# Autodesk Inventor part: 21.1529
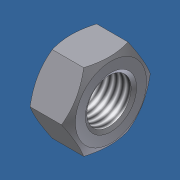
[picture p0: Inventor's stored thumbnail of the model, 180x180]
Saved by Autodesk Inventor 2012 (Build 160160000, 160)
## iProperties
Created: 2006-02
Part Number: 21.1529
Material: Steel, Mild
Description: M16 HEX NUT
Document SubType Name: Modeling
Standard: DIN 934
Designer: Andy Moles
Standards Organization: DIN
Language: en-US
Size Designation: M16
Categories: <MemberInstance><Categories><Category DisplayName="Fasteners" InternalName="e4da775c-781d-43d5-af7c-5136215cf5a6" Mnemonic="FSTN"><Category DisplayName="Nuts" I
Density: 7.86 g/cm^3
Mass: 34.481 g
Surface Area: 21.9132 cm^2
Volume: 4.38689 cm^3
Author: Andy Moles
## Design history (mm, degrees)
body "Solid1"
workaxis "Work Axis1"
workplane "Work Plane1"
sketch "Sketch1"
  geometry: L1 (-13.856, 0)-(-6.928, 12); L2 (-6.928, 12)-(6.928, 12); L3 (6.928, 12)-(13.856, 0); L4 (13.856, 0)-(6.928, -12); L5 (6.928, -12)-(-6.928, -12); L6 (-6.928, -12)-(-13.856, 0); 2 further points
  constraints: 12 end point, 1 coincident, 1 horizontal, 11 other
  dimensions: "d0" = 27.71281 distance of L3.end L1.start (= 1.1547 x SW)
extrude "Body" new body sketch "Sketch1" distance "d1" = 13 (= KOH); taper "d2" = 0 deg
revolve "Chamfer1" stored, may be unused: angle "d7" = 90 deg
sketch "Sketch3"
  geometry: 4 further points
  constraints: 1 coincident, 1 other
hole "Thread" sketch "Sketch3" diameter "d25" = 13.835; stored, may be unused: countersink angle "d29" = 82 deg, drill point angle "d31" = 118 deg; dims "d26" = 6, "d27" = 4, "d28" = 2, "d30" = 8
chamfer "Chamfer2" distance "d8" = 1.08253 (= -0.5 x GD1 + 0.5 x NND); stored, may be unused: angle "d9" = 30 deg, second distance "d40" = 1.08253 (= -0.5 x GD1 + 0.5 x NND)
chamfer "Chamfer3" distance "d10" = 1.08253 (= -0.5 x GD1 + 0.5 x NND); stored, may be unused: angle "d11" = 30 deg, second distance "d41" = 1.08253 (= -0.5 x GD1 + 0.5 x NND)
sketch "Sketch2"
  geometry: L1 (0, 6.928)-(0, 13.856) reference; L2 (0, 13.856)-(13, 13.856) reference; L3 (13, 6.928)-(13, 13.856) reference; L4 (-1.3, 0)-(16.9, 0) reference; L5 (1.591, 13.856)-(0, 11.1); L6 (11.409, 13.856)-(13, 11.1)
  constraints: 4 end point, 4 point on line
  dimensions: "d3" = 30 deg angle of L1 L5 (= ANG1); "d4" = 30 deg angle of L3 L6 (= ANG2); "d5" = 22.2 diameter of L5.end L4 (= SW0); "d6" = 22.2 diameter of L6.end L4 (= SW01)
other parameters: "ANG1" = 30 deg [user parameter; used in 1 equation term], "ANG2" = 30 deg [user parameter; used in 1 equation term], "NND" = 16 [user parameter; used in 4 equation terms], "KOH" = 13 [user parameter; used in 1 equation term], "SW" = 24 [user parameter; used in 2 equation terms], "SW0" = 22.2 (= SW01) [user parameter; used in 1 equation term], "SW01" = 22.2 [user parameter; used in 2 equation terms], "GD1" = 13.83494 (computed from THREADDIA, PTC, TOA) [user parameter; used in 4 equation terms], "d13" = 0, "d14" = 0, "d39" = 0, "d42" = 0, "GUL" = 1.08253 (= 0.541266 x PTC) [user parameter], "TPU" = 5 (computed from PTC) [user parameter], "THREADDIA" = 16 [user parameter; used in 1 equation term], "TOA" = 30 deg [user parameter; used in 1 equation term], "PTC" = 2 [user parameter; used in 4 equation terms], "E0" = 27.72 (= 1.155 x SW) [user parameter], "GAL" = 1.08253 (= 0.541266 x PTC) [user parameter]
